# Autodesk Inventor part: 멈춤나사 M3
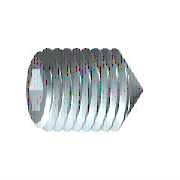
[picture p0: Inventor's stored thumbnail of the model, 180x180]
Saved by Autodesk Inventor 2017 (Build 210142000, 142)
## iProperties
IsCustomPart: 1
Created: 2012-02
Part Number: 멈춤나사 M3
Material: 강철, 연강
Description: 6각 소켓 머리 없는 멈춤 나사
Document SubType Name: Modeling
Standard: KS B 1028
Designer: test
Standards Organization: KS
Language: ko-KR
Size Designation: 원추점 M3x8
Categories: <MemberInstance><Categories><Category DisplayName="조임쇠" InternalName="e4da775c-781d-43d5-af7c-5136215cf5a6" Mnemonic="FSTN"><Category DisplayName="볼트" InternalN
Density: 1 g/cm^3
Appearance: 강철
Author: test
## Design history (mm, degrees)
sketch "스케치1"
  geometry: L1 (0, 0)-(5.5, 0); L2 (8, 0.866)-(8, 1.5); L3 (8, 1.5)-(0, 1.5); L4 (8, 0.866)-(6, 0.866); L5 (6, 0.866)-(5.5, 0); L6 (0, -0.3)-(0, 1.8) reference; L7 (0, 1.5)-(0, 0)
  constraints: 13 end point, 3 parallel, 1 collinear, 1 perpendicular, 1 point on line
  dimensions: "d0" = 2 distance of L2.start L4.end (= INTI); "d1" = 60 deg angle of L5 L1; "d2" = 3 diameter of L3 L1 (= NND); "d3" = 1.73205 diameter of L4 L1 (= 1.1547 x SW); "d5" = 8 distance from line of L2 L3.end (= NLG)
revolve "본체" sketch "스케치1" stored, may be unused: angle "d6" = 90 deg
sketch "스케치2"
  geometry: L1 (-0.433, 0.75)-(0.433, 0.75); L2 (0.433, 0.75)-(0.866, 0); L3 (0.866, 0)-(0.433, -0.75); L4 (0.433, -0.75)-(-0.433, -0.75); L5 (-0.433, -0.75)-(-0.866, 0); L6 (-0.866, 0)-(-0.433, 0.75); 3 further points
  constraints: 12 end point, 1 coincident, 1 horizontal, 13 other
extrude "슬롯" join sketch "스케치2" taper "d7" = 0 deg; stored distance "d21" = 10
workaxis "Work Axis1"
workplane "Work Plane1"
sketch "스케치4"
  geometry: L1 (0, 0.15)-(-1.35, 1.5) reference; L2 (0, -0.15)-(-1.35, -1.5) reference; L3 (-1.35, -1.5)-(0.15, 0); L4 (-1.35, 1.5)-(0.15, 0); 2 further points
  constraints: 4 end point, 1 coincident, 1 collinear, 1 horizontal alignment
body "Solid1"
feature "스레드" dims "d12" = 8 (= NLG), "d13" = 0
chamfer "모따기1" distance "d8" = 1.35 (computed from NND, SPD, FAWI); stored, may be unused: angle "d9" = 45 deg (= FAWI), second distance "d34" = 1.35 (computed from NND, SPD, FAWI)
chamfer "모따기2" distance "d10" = 0.30673 (= -0.5 x GD1 + 0.5 x NND); stored, may be unused: angle "d11" = 45 deg (= FAWI), second distance "d35" = 0.30673 (= -0.5 x GD1 + 0.5 x NND)
other parameters: "NND" = 3 [user parameter; used in 5 equation terms], "NLG" = 8 [user parameter; used in 2 equation terms], "INTI" = 2 [user parameter; used in 1 equation term], "FAWI" = 45 deg [user parameter; used in 4 equation terms], "SW" = 1.5 [user parameter; used in 2 equation terms], "GD1" = 2.38655 (= THREADDIA - 1.2269 x PTC) [user parameter; used in 2 equation terms], "d4" = 0, "FAWI1" = 45 deg [user parameter], "SPD" = 0.3 [user parameter; used in 2 equation terms], "d36" = 0, "d37" = 0, "GUL" = 0.30673 (= 0.61345 x PTC) [user parameter], "TOA" = 30 deg [user parameter], "THREADDIA" = 3 [user parameter; used in 1 equation term], "PTC" = 0.5 [user parameter; used in 4 equation terms], "GAL" = 0.30673 (= 0.61345 x PTC) [user parameter], "E0" = 1.7325 (= 1.155 x SW) [user parameter]
